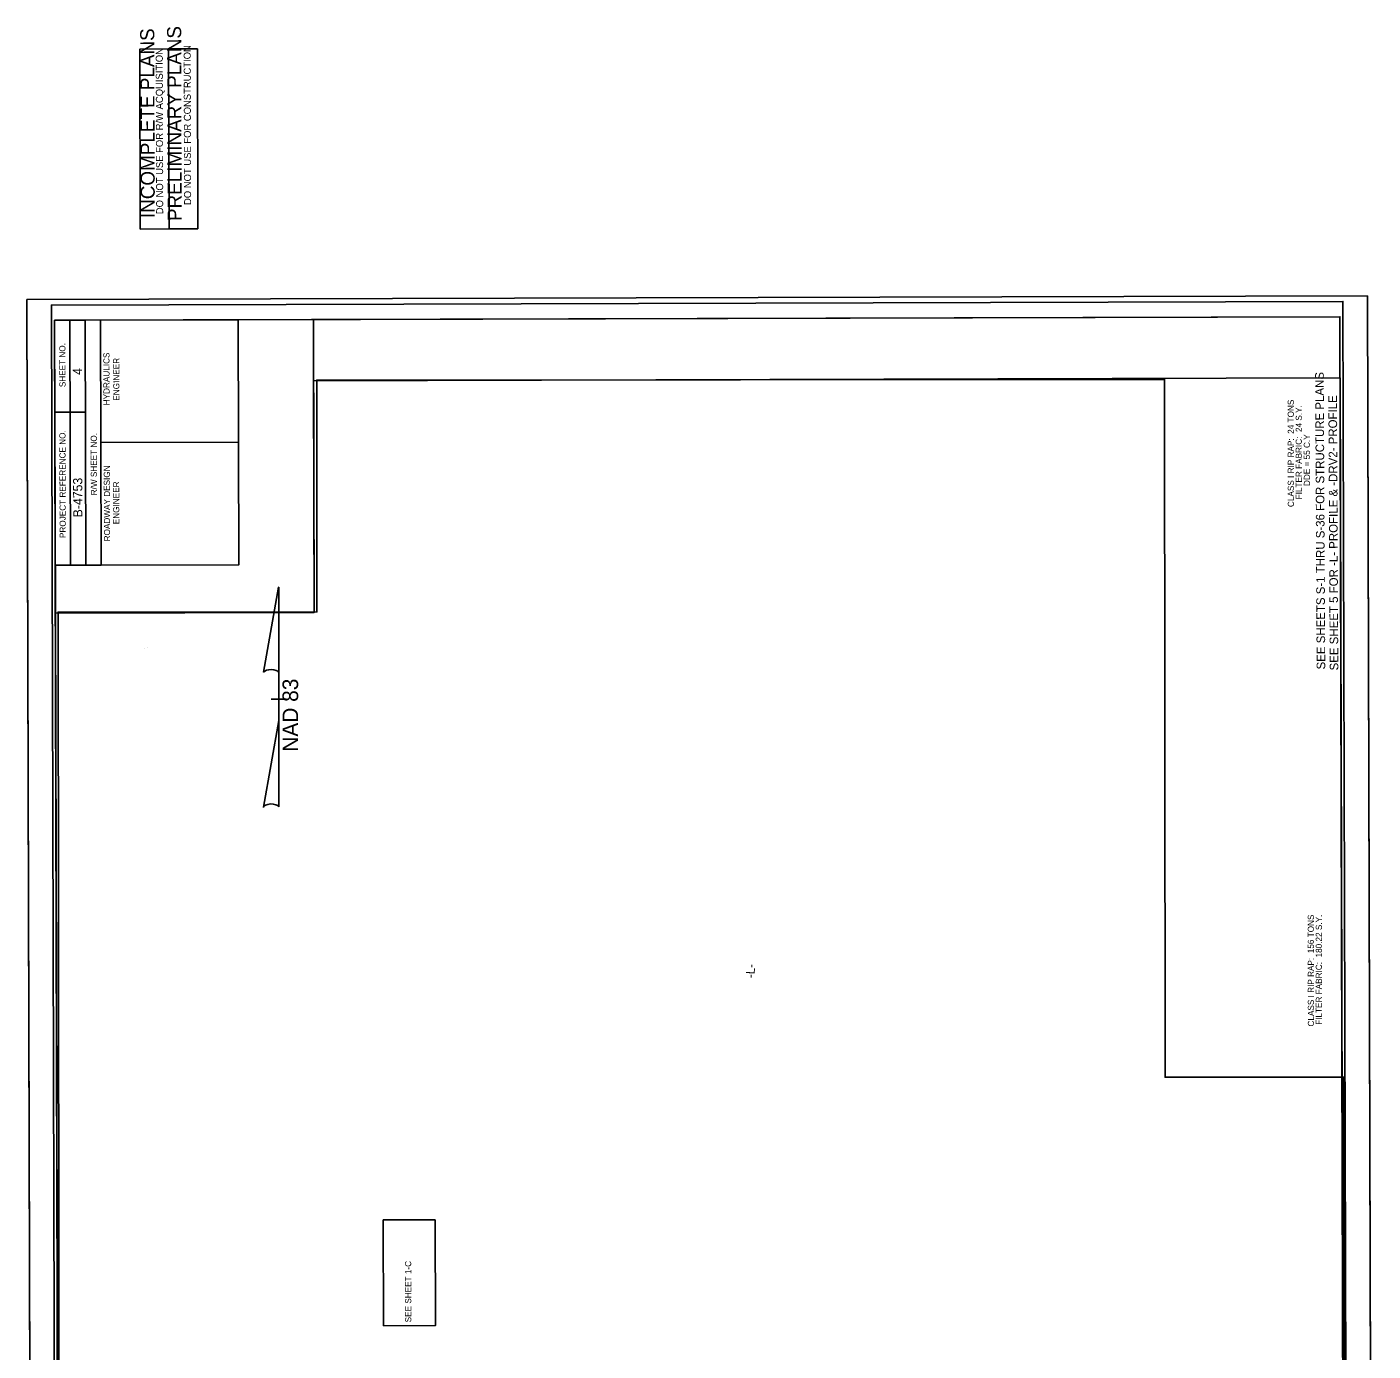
# Model space of a CAD drawing. Extents: x 1373110 to 1374209, y 550682 to 552749.
# Drawn here: x 1373110 to 1374209, y 551668 to 552749 of the extents above; entities that cross this region are included whole.
import ezdxf

# ---------------------------------------------------------------- set-up
doc = ezdxf.new("R2010")
doc.units = 0
for name, color, linetype in [('Default', 7, 'Continuous'), ('Prop Conc Shoulder Berm Gutter', 7, 'Continuous'), ('Prop Drainage Structure Drop Inlet Grate 2 Narrow Slots and Flat Grates 840 29 TB Label', 7, 'Continuous'), ('Prop Drainage Structure Gutter Shoulder Berm Label', 7, 'Continuous'), ('Prop Drainage Structure Pipe Alternate 15in', 7, 'Continuous'), ('Prop Drainage Structure Pipe Alternate 15in Label', 7, 'Continuous'), ('Prop Drainage Structure Pipe CSP 15in Label', 7, 'Continuous'), ('Prop Drainage Structure Pipe RCP 15in Class IV Label', 7, 'Continuous'), ('Prop Drainage Structure Retain Label', 7, 'Continuous'), ('Prop Drainage Structure Tops and Inverts LABEL', 7, 'Continuous'), ('Prop Earthen Structure Base Ditch Special Lateral with Rip Rap Detail CELL', 7, 'Continuous'), ('Prop Earthen Structure Base Ditch with Rip Rap Detail CELL', 7, 'Continuous'), ('Prop Earthen Structure Base Ditch with Rip Rap Detail Label', 7, 'Continuous'), ('Prop Erosion Rip Rap Class B', 7, 'Continuous'), ('Prop Erosion Rip Rap Class B Label', 7, 'Continuous'), ('Prop Plan Preparation Sketches Hydraulic Ditch', 7, 'Continuous'), ('Typical Terminator CELL', 7, 'Continuous')]:
    doc.layers.add(name, color=color, linetype=linetype)

msp = doc.modelspace()

# ---------------------------------------------------------------- linework, layer by layer
at = {"layer": 'Default'}
msp.add_line((1373207.9, 552242.7), (1373207.9, 552242.7), dxfattribs=at)
at = {"layer": 'Prop Drainage Structure Drop Inlet Grate 2 Narrow Slots and Flat Grates 840 29 TB Label'}
for p, q in [((1373145.2, 552309.7), (1373144.7, 552509.8)), ((1373157.7, 552309.8), (1373157.2, 552509.8)), ((1373157.7, 552309.8), (1373157.2, 552509.8)), ((1373132.4, 552434.7), (1373157.4, 552434.8)), ((1373169.9, 552409.8), (1373282.4, 552410.2)), ((1373157.7, 552309.8), (1373170.2, 552309.8))]:
    msp.add_line(p, q, dxfattribs=at)
for points in [[(1373132.1, 552509.8), (1373136.2, 551009.7), (1374186.2, 551012.6), (1374182.1, 552512.6)], [(1373132.6, 552309.7), (1373132.1, 552509.8), (1373157.2, 552509.8), (1373157.7, 552309.8)], [(1374186.2, 551012.6), (1373136.2, 551009.7), (1373132.6, 552309.7), (1373282.7, 552310.1), (1373282.2, 552510.1), (1374182.1, 552512.6)], [(1373169.9, 552409.8), (1373169.7, 552509.8), (1373282.2, 552510.1), (1373282.4, 552410.1)], [(1373170.2, 552309.8), (1373169.9, 552409.8), (1373282.4, 552410.1), (1373282.7, 552310.1)]]:
    msp.add_lwpolyline(points, close=True, dxfattribs=at)
at = {"layer": 'Prop Drainage Structure Gutter Shoulder Berm Label'}
msp.add_lwpolyline([(1374209.2, 550846.2), (1374204.6, 552529.7), (1373109.6, 552526.7), (1373114.2, 550843.2)], close=True, dxfattribs=at)
at = {"layer": 'Prop Drainage Structure Pipe Alternate 15in'}
msp.add_lwpolyline([(1373249.2, 552584.3), (1373225.7, 552584.3), (1373225.3, 552731.3), (1373248.8, 552731.3)], close=True, dxfattribs=at)
at = {"layer": 'Prop Drainage Structure Pipe Alternate 15in Label'}
msp.add_lwpolyline([(1373225.7, 552584.3), (1373202.2, 552584.2), (1373201.8, 552731.2), (1373225.3, 552731.3)], close=True, dxfattribs=at)
at = {"layer": 'Prop Drainage Structure Pipe CSP 15in Label'}
for p, q in [((1374209.2, 550846.2), (1374204.6, 552529.7)), ((1373109.6, 552526.7), (1373114.2, 550843.2))]:
    msp.add_line(p, q, dxfattribs=at)
at = {"layer": 'Prop Drainage Structure Pipe RCP 15in Class IV Label'}
for points in [[(1373344.2, 552271), (1373343.6, 552510.3), (1373132.1, 552509.8), (1373132.8, 552270.5)], [(1373136.2, 551009.7), (1374186.2, 551012.6), (1374182.1, 552512.6), (1373343.6, 552510.3), (1373344.2, 552271), (1373132.8, 552270.5)]]:
    msp.add_lwpolyline(points, close=True, dxfattribs=at)
at = {"layer": 'Prop Drainage Structure Tops and Inverts LABEL'}
msp.add_lwpolyline([(1374189.1, 550859.1), (1374184.6, 552525.1), (1373129.6, 552522.2), (1373134.1, 550856.2)], close=True, dxfattribs=at)
at = {"layer": 'Prop Earthen Structure Base Ditch Special Lateral with Rip Rap Detail CELL'}
for p, q in [((1373205.8, 552241.8), (1373205.8, 552241.8)), ((1373207.9, 552242.7), (1373207.9, 552242.7))]:
    msp.add_line(p, q, dxfattribs=at)
at = {"layer": 'Prop Earthen Structure Base Ditch with Rip Rap Detail CELL'}
msp.add_lwpolyline([(1374186.1, 551062.6), (1374182.2, 552462.6), (1373343.7, 552460.3), (1373344.2, 552271), (1373132.8, 552270.5), (1373136.1, 551059.7)], close=True, dxfattribs=at)
at = {"layer": 'Prop Erosion Rip Rap Class B Label'}
for points in [[(1374186.1, 551062.6), (1374182.2, 552462.6), (1373343.7, 552460.3), (1373344.2, 552271), (1373132.8, 552270.5), (1373136.1, 551059.7)], [(1374186.1, 551055.1), (1374185.3, 551891.7), (1374039.3, 551891.5), (1374038.8, 552461.5), (1373346.3, 552460.9), (1373346.5, 552271.6), (1373135, 552271.4), (1373135.8, 551468.7), (1373357.2, 551468.9), (1373357.6, 551054.3)]]:
    msp.add_lwpolyline(points, close=True, dxfattribs=at)
at = {"layer": 'Prop Plan Preparation Sketches Hydraulic Ditch'}
msp.add_lwpolyline([(1373400.8, 551688.6), (1373400.6, 551775), (1373443, 551775.1), (1373443.3, 551688.7)], close=True, dxfattribs=at)
at = {"layer": 'Typical Terminator CELL'}
for p, q in [((1373302.9, 552222.3), (1373315.2, 552291.9)), ((1373315.3, 552291.9), (1373315.2, 552291.9)), ((1373315.3, 552291.9), (1373315.2, 552291.9)), ((1373315.3, 552291.9), (1373315.3, 552220.2)), ((1373315.3, 552183), (1373315.3, 552222.3)), ((1373315.3, 552220.2), (1373315.3, 552222.2)), ((1373309.3, 552200.4), (1373309.2, 552200.4)), ((1373314.6, 552200.4), (1373309.3, 552200.4)), ((1373309.4, 552200.4), (1373321.4, 552200.4)), ((1373315.3, 552183), (1373302.8, 552112.1)), ((1373315.4, 552112.4), (1373315.3, 552183))]:
    msp.add_line(p, q, dxfattribs=at)
for centre, start_param, end_param in [((1373309.1, 552221.6), 0.216388, 2.908219), ((1373309.1, 552111.8), 0.201328, 3.141593)]:
    msp.add_ellipse(centre, major_axis=(6.34, -0.05), ratio=0.461098, start_param=start_param, end_param=end_param, dxfattribs=at)

# ---------------------------------------------------------------- texts
at = {"layer": 'Prop Conc Shoulder Berm Gutter'}
for s, p in [(' 4 ', (1373154.5, 552462.4)), (' B-4753  ', (1373154.9, 552346))]:
    msp.add_text(s, height=7.5, rotation=90.1567, dxfattribs=at).set_placement(p)
at = {"layer": 'Prop Drainage Structure Drop Inlet Grate 2 Narrow Slots and Flat Grates 840 29 TB Label'}
for s, p in [('SHEET NO.', (1373141.1, 552455.1)), ('HYDRAULICS', (1373177.1, 552440.3)), ('ENGINEER', (1373185.1, 552444.1)), ('PROJECT REFERENCE NO.', (1373141.3, 552331.9)), ('R/W SHEET NO.', (1373166.8, 552366.8)), ('ROADWAY DESIGN', (1373177.5, 552329.2)), ('ENGINEER', (1373185, 552343.2))]:
    msp.add_text(s, height=5, rotation=90.1567, dxfattribs=at).set_placement(p)
at = {"layer": 'Prop Drainage Structure Pipe Alternate 15in'}
for s, height, p in [('PRELIMINARY PLANS', 11.52, (1373236, 552590.8)), ('DO NOT USE FOR CONSTRUCTION', 5.76, (1373243.7, 552603.9))]:
    msp.add_text(s, height=height, rotation=90.1567, dxfattribs=at).set_placement(p)
at = {"layer": 'Prop Drainage Structure Pipe Alternate 15in Label'}
for s, height, p in [('INCOMPLETE PLANS', 11.52, (1373214, 552593.2)), ('DO NOT USE FOR R/W ACQUISITION', 5.76, (1373220.9, 552596.4))]:
    msp.add_text(s, height=height, rotation=90.1567, dxfattribs=at).set_placement(p)
at = {"layer": 'Prop Drainage Structure Retain Label'}
msp.add_text('-L-', height=7, rotation=86.7262, dxfattribs=at).set_placement((1373703.8, 551972.4))
at = {"layer": 'Prop Earthen Structure Base Ditch with Rip Rap Detail Label'}
for s, p in [('CLASS I RIP RAP:  24 TONS', (1374144.5, 552357.2)), ('FILTER FABRIC:  24 S.Y.', (1374151, 552363.5)), ('DDE = 55 C.Y', (1374157.6, 552374.4)), ('CLASS I RIP RAP:  156 TONS   ', (1374160.9, 551933)), ('FILTER FABRIC:  180.22 S.Y. ', (1374167.4, 551934.4)), ('SEE SHEET 1-C', (1373423.5, 551691.4))]:
    msp.add_text(s, height=5, rotation=90.0509, dxfattribs=at).set_placement(p)
at = {"layer": 'Prop Erosion Rip Rap Class B'}
for s, p in [('SEE SHEETS S-1 THRU S-36 FOR STRUCTURE PLANS', (1374170.1, 552224.6)), ('SEE SHEET 5 FOR -L- PROFILE & -DRV2- PROFILE', (1374180.8, 552223.8))]:
    msp.add_text(s, height=7, rotation=90.2952, dxfattribs=at).set_placement(p)
at = {"layer": 'Typical Terminator CELL'}
msp.add_text('NAD 83', height=12.75, rotation=90, dxfattribs=at).set_placement((1373331.1, 552157.4))

doc.saveas('drawing.dxf')
